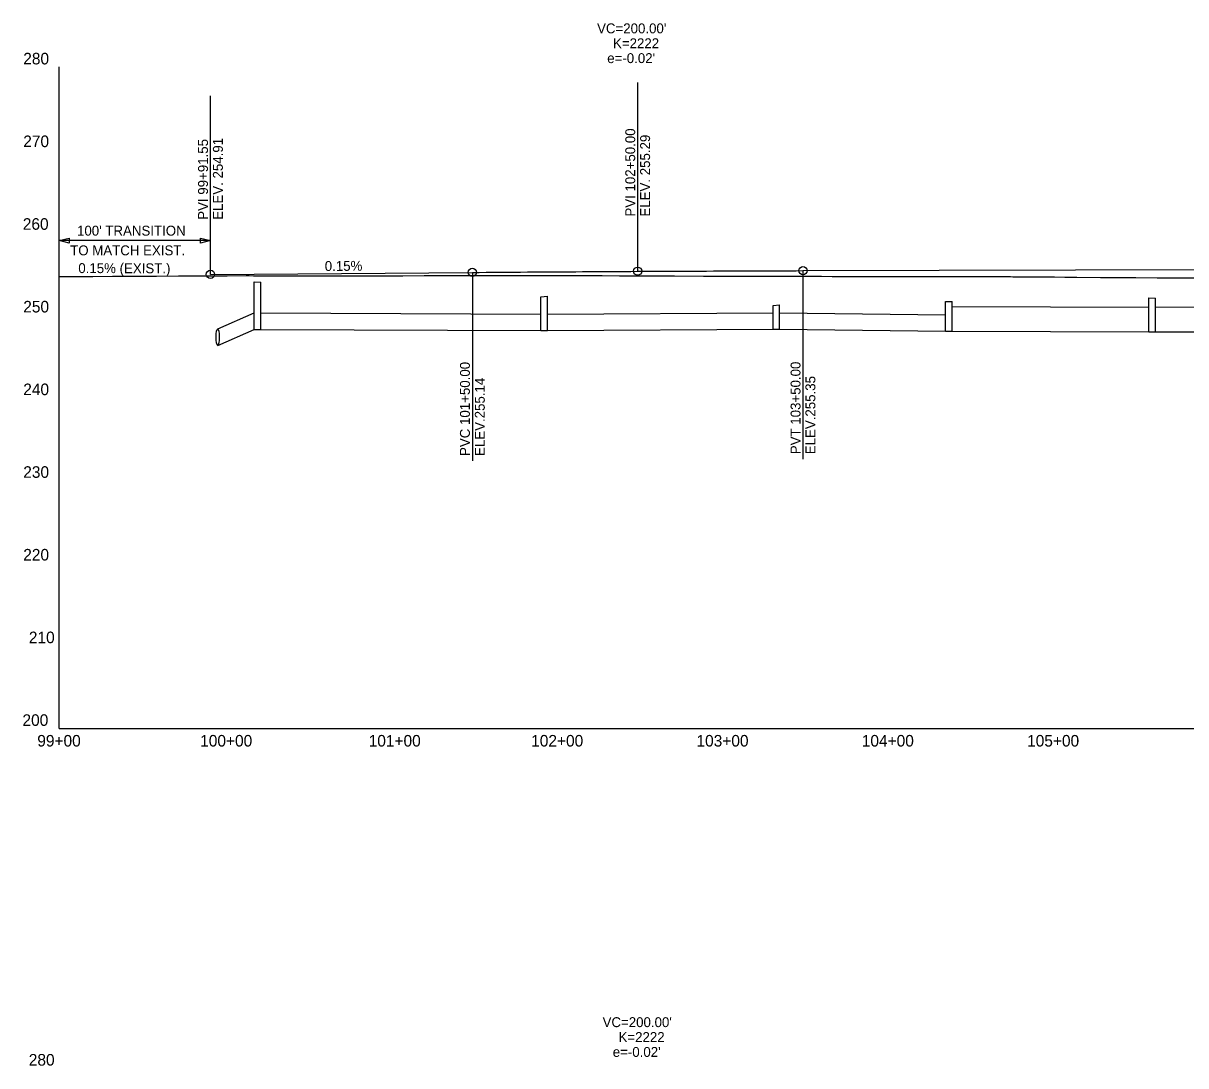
# Model space of a CAD drawing. Extents: x 1930770 to 1938778, y 596900 to 600561.
# Drawn here: x 1932134 to 1932838, y 599461 to 600091 of the extents above; entities that cross this region are included whole.
import ezdxf

# ---------------------------------------------------------------- set-up
doc = ezdxf.new("R2010")
doc.units = 0
for name, color, linetype in [('S_CROSS_DRAIN_ANNOT', 7, 'Continuous'), ('S_DROP_INLET_ANNOT', 7, 'Continuous'), ('S_ELECTRIC_UTILITIES_ANNOT', 7, 'Continuous'), ('S_HIST_HIGH_WATER_ANNOT', 7, 'Continuous'), ('S_SIGN_ANNOT', 7, 'Continuous'), ('S_STORM_SEWER_ANNOT', 7, 'Continuous'), ('S_WATER_UTILITIES_ANNOT', 7, 'Continuous')]:
    doc.layers.add(name, color=color, linetype=linetype)

msp = doc.modelspace()

# ---------------------------------------------------------------- linework, layer by layer
at = {"layer": 'S_CROSS_DRAIN_ANNOT'}
for q in [(1932156.02, 600064.63), (1933656.02, 599664.63)]:
    msp.add_line((1932156.02, 599664.63), q, dxfattribs=at)
at = {"layer": 'S_ELECTRIC_UTILITIES_ANNOT'}
for p, q in [((1932506.02, 599971.11), (1932506.02, 600055.11)), ((1932247.57, 599969.17), (1932247.57, 600047.17)), ((1932506.02, 599941.11), (1932506.02, 599971.11)), ((1932247.57, 599939.17), (1932247.57, 599969.17)), ((1932506.02, 599941.11), (1932556.02, 599941.26)), ((1932606.02, 599941.41), (1932606.02, 599911.41)), ((1932406.02, 599940.36), (1932406.02, 599910.36)), ((1932456.02, 599940.73), (1932506.02, 599941.11)), ((1932406.02, 599910.36), (1932406.02, 599826.36)), ((1932606.02, 599911.41), (1932606.02, 599827.41))]:
    msp.add_line(p, q, dxfattribs=at)
for centre in [(1932247.57, 599939.17), (1932406.02, 599940.36), (1932506.02, 599941.11), (1932606.02, 599941.41)]:
    msp.add_circle(centre, 2.5, dxfattribs=at)
at = {"layer": 'S_HIST_HIGH_WATER_ANNOT'}
for p, q in [((1932606.02, 599941.41), (1933204.02, 599943.2)), ((1932247.57, 599939.17), (1932406.02, 599940.36))]:
    msp.add_line(p, q, dxfattribs=at)
msp.add_lwpolyline([(1932406.02, 599940.36), (1932410.19, 599940.39), (1932414.36, 599940.42), (1932418.52, 599940.45), (1932422.69, 599940.48), (1932426.86, 599940.51), (1932431.02, 599940.54), (1932435.19, 599940.57), (1932439.36, 599940.6), (1932443.52, 599940.62), (1932447.69, 599940.65), (1932451.86, 599940.68), (1932456.02, 599940.71), (1932460.19, 599940.73), (1932464.36, 599940.76), (1932468.52, 599940.78), (1932472.69, 599940.81), (1932476.86, 599940.83), (1932481.02, 599940.86), (1932485.19, 599940.88), (1932489.36, 599940.91), (1932493.52, 599940.93), (1932497.69, 599940.95), (1932501.86, 599940.97), (1932510.19, 599941.02), (1932514.36, 599941.04), (1932518.52, 599941.06), (1932522.69, 599941.08), (1932526.86, 599941.1), (1932531.02, 599941.12), (1932535.19, 599941.14), (1932539.36, 599941.16), (1932543.52, 599941.18), (1932547.69, 599941.2), (1932551.86, 599941.21), (1932556.02, 599941.23), (1932560.19, 599941.25), (1932564.36, 599941.26), (1932568.52, 599941.28), (1932572.69, 599941.3), (1932576.86, 599941.31), (1932581.02, 599941.33), (1932585.19, 599941.34), (1932589.36, 599941.36), (1932593.52, 599941.37), (1932597.69, 599941.38), (1932601.86, 599941.4), (1932606.02, 599941.41)], dxfattribs=at)
at = {"layer": 'S_SIGN_ANNOT'}
for p, q in [((1932274.02, 599905.88), (1932274.02, 599934.56)), ((1932274.02, 599934.56), (1932278.02, 599934.5)), ((1932278.02, 599905.88), (1932278.02, 599934.5)), ((1932447.44, 599925.63), (1932451.44, 599925.92)), ((1932447.44, 599905.18), (1932447.44, 599925.63)), ((1932451.44, 599905.18), (1932451.44, 599925.92)), ((1932587.91, 599920.39), (1932591.91, 599920.81)), ((1932587.91, 599905.98), (1932587.91, 599920.39)), ((1932591.91, 599905.98), (1932591.91, 599920.81)), ((1932692.33, 599922.76), (1932696.33, 599922.8)), ((1932692.33, 599904.78), (1932692.33, 599922.76)), ((1932696.33, 599904.78), (1932696.33, 599922.8)), ((1932815.18, 599904.33), (1932815.18, 599924.94)), ((1932815.18, 599924.94), (1932819.18, 599924.76)), ((1932819.18, 599904.33), (1932819.18, 599924.76)), ((1932251.94, 599906.23), (1932274.02, 599915.88)), ((1932278.02, 599915.88), (1932447.44, 599915.18)), ((1932451.44, 599915.18), (1932587.91, 599915.98)), ((1932591.91, 599915.98), (1932692.33, 599914.78)), ((1932696.33, 599919.78), (1932815.18, 599919.33)), ((1932819.18, 599919.33), (1932897.73, 599919.58)), ((1932251.94, 599896.23), (1932274.02, 599905.88)), ((1932274.02, 599905.88), (1932278.02, 599905.88)), ((1932278.02, 599905.88), (1932447.44, 599905.18)), ((1932447.44, 599905.18), (1932451.44, 599905.18)), ((1932451.44, 599905.18), (1932587.91, 599905.98)), ((1932587.91, 599905.98), (1932591.91, 599905.98)), ((1932591.91, 599905.98), (1932692.33, 599904.78)), ((1932692.33, 599904.78), (1932696.33, 599904.78)), ((1932696.33, 599904.78), (1932815.18, 599904.33)), ((1932815.18, 599904.33), (1932819.18, 599904.33)), ((1932819.18, 599904.33), (1932897.73, 599904.58))]:
    msp.add_line(p, q, dxfattribs=at)
msp.add_ellipse((1932251.94, 599901.23), major_axis=(0, 5), ratio=0.2, dxfattribs=at)
at = {"layer": 'S_STORM_SEWER_ANNOT'}
for p, q in [((1932156.03, 599939.13), (1932156.03, 599962.6)), ((1932247.57, 599939.13), (1932247.57, 599962.6)), ((1932247.57, 599959.6), (1932156.03, 599959.6))]:
    msp.add_line(p, q, dxfattribs=at)
for points in [[(1932162.03, 599958.1), (1932156.03, 599959.6), (1932162.03, 599961.1)], [(1932241.57, 599961.1), (1932247.57, 599959.6), (1932241.57, 599958.1)]]:
    msp.add_lwpolyline(points, close=True, dxfattribs=at)
at = {"layer": 'S_WATER_UTILITIES_ANNOT'}
msp.add_lwpolyline([(1932156.02, 599937.89), (1932161.49, 599937.82), (1932162.57, 599937.81), (1932163.64, 599937.81), (1932175.43, 599937.89), (1932176.45, 599937.9), (1932188.29, 599937.98), (1932189.26, 599937.98), (1932201.15, 599938.06), (1932202.08, 599938.06), (1932214.02, 599938.14), (1932215, 599938.14), (1932228.24, 599938.21), (1932229.25, 599938.21), (1932242.46, 599938.28), (1932243.5, 599938.27), (1932247.58, 599938.3), (1932256.68, 599938.34), (1932257.77, 599938.34), (1932269.11, 599938.4), (1932270.91, 599938.4), (1932273.57, 599938.31), (1932273.85, 599938.31), (1932274.07, 599938.31), (1932274.87, 599938.31), (1932286.67, 599938.34), (1932287.55, 599938.34), (1932290.65, 599938.33), (1932299.19, 599938.32), (1932300.16, 599938.31), (1932311.72, 599938.3), (1932312.18, 599938.3), (1932312.76, 599938.29), (1932324.24, 599938.27), (1932325.39, 599938.27), (1932333.71, 599938.25), (1932336.77, 599938.25), (1932339.26, 599938.25), (1932355.25, 599938.32), (1932361.14, 599938.34), (1932364.03, 599938.35), (1932376.78, 599938.39), (1932385.52, 599938.42), (1932387.29, 599938.43), (1932398.28, 599938.46), (1932398.31, 599938.46), (1932400.17, 599938.46), (1932411.04, 599938.49), (1932413.08, 599938.5), (1932419.85, 599938.51), (1932423.79, 599938.52), (1932426, 599938.53), (1932436.56, 599938.55), (1932441.38, 599938.54), (1932453.61, 599938.49), (1932457.71, 599938.48), (1932462.91, 599938.46), (1932474.33, 599938.42), (1932478.86, 599938.4), (1932484.45, 599938.38), (1932494.98, 599938.34), (1932500.01, 599938.32), (1932505.98, 599938.3), (1932515.55, 599938.25), (1932521.17, 599938.23), (1932527.52, 599938.22), (1932528.3, 599938.22), (1932545.93, 599938.17), (1932549.05, 599938.17), (1932554.75, 599938.16), (1932570.58, 599938.11), (1932570.64, 599938.11), (1932580.79, 599938.1), (1932592.12, 599938.06), (1932593.96, 599938.05), (1932606.03, 599938.01), (1932613.65, 599938), (1932617.32, 599937.99), (1932623.74, 599937.96), (1932630.94, 599937.96), (1932635.18, 599937.94), (1932636.79, 599937.93), (1932644.55, 599937.93), (1932652.96, 599937.92), (1932656.72, 599937.9), (1932658.15, 599937.9), (1932667.19, 599937.89), (1932671.74, 599937.87), (1932678.25, 599937.87), (1932689.78, 599937.86), (1932696.14, 599937.89), (1932699.78, 599937.88), (1932716.19, 599937.86), (1932720.53, 599937.88), (1932721.32, 599937.87), (1932731.46, 599937.79), (1932733.06, 599937.77), (1932742.85, 599937.7), (1932744.58, 599937.69), (1932745.58, 599937.68), (1932757.71, 599937.59), (1932758.1, 599937.58), (1932764.39, 599937.53), (1932766.25, 599937.52), (1932770.61, 599937.47), (1932771.73, 599937.47), (1932785.92, 599937.35), (1932795.39, 599937.27), (1932803.51, 599937.24), (1932807.45, 599937.21), (1932820.21, 599937.12), (1932828.99, 599937.05), (1932834.28, 599937.02), (1932843.89, 599936.98)], dxfattribs=at)

# ---------------------------------------------------------------- texts
at = {"layer": 'S_DROP_INLET_ANNOT'}
for s, p in [('280', (1932134.33, 600066.13)), ('280', (1932134.33, 600066.13)), ('270', (1932134.33, 600016.13)), ('260', (1932134.05, 599966.13)), ('250', (1932134.33, 599916.13)), ('240', (1932134.33, 599866.13)), ('230', (1932134.33, 599816.13)), ('220', (1932134.33, 599766.13)), ('210', (1932137.73, 599716.13)), ('200', (1932133.86, 599666.13)), ('99+00', (1932142.82, 599653.63)), ('100+00', (1932241.36, 599653.63)), ('101+00', (1932343.29, 599653.63)), ('102+00', (1932441.59, 599653.63)), ('103+00', (1932541.59, 599653.63)), ('104+00', (1932641.59, 599653.63)), ('105+00', (1932741.59, 599653.63)), ('280', (1932137.68, 599460.71)), ('280', (1932137.68, 599460.71))]:
    msp.add_text(s, height=7, dxfattribs=at).set_placement(p)
at = {"layer": 'S_ELECTRIC_UTILITIES_ANNOT'}
for s, p in [("VC=200.00'", (1932481.46, 600084.92)), ('K=2222', (1932491.1, 600075.92)), ("e=-0.02'", (1932487.6, 600066.92)), ("VC=200.00'", (1932484.8, 599483.96)), ('K=2222', (1932494.44, 599474.96)), ("e=-0.02'", (1932490.95, 599465.96))]:
    msp.add_text(s, height=6, dxfattribs=at).set_placement(p)
for s, rotation, p in [('PVI 102+50.00', 90, (1932504.52, 599974.11)), ('PVI 99+91.55', 90, (1932246.07, 599972.17)), ('ELEV. 254.91', 90, (1932255.07, 599972.17)), ('ELEV. 255.29', 90, (1932513.52, 599974.11)), ('0.15% (EXIST.)', 359.84683, (1932167.63, 599939.95)), ('0.15%', 0.42971, (1932316.75, 599941.19)), ('PVC 101+50.00', 90, (1932404.52, 599829.36)), ('PVT 103+50.00', 90, (1932604.52, 599830.41)), ('ELEV.255.14', 90, (1932413.52, 599829.36)), ('ELEV.255.35', 90, (1932613.52, 599830.41))]:
    msp.add_text(s, height=6, rotation=rotation, dxfattribs=at).set_placement(p)
at = {"layer": 'S_STORM_SEWER_ANNOT'}
for s, p in [("100' TRANSITION", (1932166.86, 599962.58)), ('TO MATCH EXIST.', (1932162.72, 599950.68))]:
    msp.add_text(s, height=6, rotation=0.00482, dxfattribs=at).set_placement(p)
msp.add_text('-', height=0.0001, dxfattribs=at).set_placement((1932156.02, 599664.63))

doc.saveas('drawing.dxf')
